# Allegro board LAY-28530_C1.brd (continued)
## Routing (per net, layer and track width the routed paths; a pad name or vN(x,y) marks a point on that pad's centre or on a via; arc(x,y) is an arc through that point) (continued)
N24275210: length 20.7
  TOP w0.127: U21.Y16 134.6,60.81 v2(134.2,60.41)
  BOTTOM w0.305: C464.1 125.66,55.04 131.03,60.41 v2(134.2,60.41)
  BOTTOM w0.381: R330.1 117.02,55.17 117.4,55.55 C467.1 121.47,55.55 121.98,55.04 C465.1 C464.1
N24275332: length 8.1
  BOTTOM w0.381: C328.2 C329.2 120.2,72.06 C330.2 R305.1
N24275468: length 8.1
  BOTTOM w0.381: C464.2 C465.2 122.23,53.52 121.47,52.75 C467.2 R336.1
N24288324: length 28.3
  TOP w0.203: U5.12 v1(101.24,137.59) ; U5.1 v1(105.63,137.59)
  L4_INT2 w0.508: v1(101.24,137.59) 102,136.83 104.87,136.83 v1(105.63,137.59)
  BOTTOM w0.508: C203.2 105.34,137.29 v1(105.63,137.59) 106.99,137.59 108.26,136.32 108.26,134.29 106.61,132.64 106.61,125.02 105.85,124.25 R225.1 R226.2 ; v1(101.24,137.59) 101.28,137.55 C206.2
N24289313: length 9.4
  TOP w0.508: R66.1 R74.1 C48.1 C51.2 105.34,122.35 104.58,123.11 L14.2
N24289334: length 4
  TOP w0.203: 104.2,129.72 104.03,129.88 U5.32
  TOP w0.508: L14.1 104.58,129.33 104.2,129.72
N24291582: length 12.2
  TOP w0.203: U5.45 107.13,134.78 107.75,134.16 R40.1 108.39,133.53 108.77,133.14 v1(109.02,133.14) 109.53,133.14 110.67,132 110.67,131.62 111.05,131.24 C36.1 115.25,131.24 115.54,131.53 Y2.1
N24291591: length 8.4
  TOP w0.203: Y2.3 113.13,134.63 112.83,134.92 v1(112.83,135.3) 112.45,135.68 C26.1 R40.2 108.13,135.68 107.63,135.18 U5.46
N24291955: length 5.8
  TOP w0.152: R59.1 98.74,129.21 v1(99.62,129.21) 100.51,129.21 101.63,130.33 U5.26
  BOTTOM w0.152: R217.1 98.74,128.45 99.5,129.21 v1(99.62,129.21)
N24292790: length 3.2
  TOP w0.203: U5.48 106.9,135.98 108.26,137.34 109.02,137.34
N24294529: length 3.4
  BOTTOM w0.254: D12.2 115.08,5.38 R401.2
N24294558: length 5.2
  BOTTOM w0.203: R396.2 C607.1
  BOTTOM w0.254: C607.1 114.1,7.29 114.39,7 D12.1
N24301989: length 27.2
  TOP w0.203: v1(122.23,137.72) 122.24,137.72 122.44,137.51 U6.12 ; v1(126.84,137.68) U6.1
  L3_INT1 w0.508: v1(122.23,137.72) 122.23,137.34 122.61,136.95 126.04,136.95 126.76,137.68 v1(126.84,137.68) 127.31,137.21 127.31,127.05 v1(124.39,124.13)
  BOTTOM w0.508: C201.2 122.48,137.46 v1(122.23,137.72) ; v1(124.39,124.13) R223.1 R224.2 ; C202.2 126.68,137.51 v1(126.84,137.68)
N24302177: length 11.2
  TOP w0.381: L15.2 127.95,124.89 ; L15.2 130.11,124.03 ; L15.2 125.79,124.03
  TOP w0.508: 130.61,124.38 C46.1 R71.1 130.61,126.16 ; 128.2,122.98 127.95,123.24 L15.2 ; R64.1 130.61,127.81 ; C50.2 130.61,122.98
N24302183: length 5.2
  TOP w0.203: 125.37,129.88 125.24,130 U6.32
  TOP w0.508: L15.1 127.95,127.68 127.31,128.32 126.93,128.32 125.37,129.88
N24302493: length 10.2
  TOP w0.203: Y1.1 135.1,133.06 C33.1 v1(133.91,133.02) 133.41,133.53 130.87,133.53 130.1,134.29 R39.1 129.22,134.29 128.72,134.78 U6.45
N24302533: length 7
  TOP w0.203: Y1.3 132.47,137.17 v1(132.14,136.83) 131.5,136.19 C25.1 R39.2 129.47,135.81 128.84,135.18 U6.46
N24302727: length 2.9
  TOP w0.203: R28.2 129.09,137.46 128.58,136.95 128.58,136.45 128.11,135.98 U6.48
N24303060: length 6.8
  BOTTOM w0.254: D13.2 121.47,6.99 R395.2
N24303062: length 5.1
  BOTTOM w0.203: C604.1 R394.2
  BOTTOM w0.254: R394.2 124.01,7.01 D13.1
N24307470: length 3.8
  TOP w0.104: U6.40 128.26,132.78 128.3,132.83 128.49,132.83 v1(128.95,132.37) 129.08,132.37 129.38,132.68 129.51,132.68 129.96,132.23 130.38,132.23 C37.2
N24307585: length 3.9
  TOP w0.104: U6.41 128.26,133.18 128.3,133.13 128.89,133.13 129.04,133.28 v1(129.04,133.41) 129.11,133.35 129.27,133.35 130.08,132.53 130.38,132.53 C30.2
N24320723: length 7.4
  TOP w0.127: U21.W3 v2(135,71.61)
  BOTTOM w0.127: v2(135,71.61) 134.6,72.01 134.6,72.58 134.6,73.5
  BOTTOM w0.152: R278.2 133.91,77.52 133.91,75.87 134.3,75.49 R288.2 134.55,75.07 134.6,75.03 134.6,73.5
N24320726: length 5.8
  TOP w0.127: U21.T4 v2(137.4,70.81)
  BOTTOM w0.104: 138.74,73.58 138.74,73.45
  BOTTOM w0.127: v2(137.4,70.81) 137.4,70.84 138.11,71.55 C331.1 138.11,72.82
  BOTTOM w0.152: 138.74,73.45 138.11,72.82 ; R285.2 138.74,73.58
N24320797: length 8.4
  TOP w0.127: U21.V5 v2(135.8,70.01)
  BOTTOM w0.122: 131.37,72.06 131.63,71.8 132.39,71.8 133,71.19 133,70.56 133.15,70.41
  BOTTOM w0.127: v2(135.8,70.01) 135.4,70.41 133.15,70.41
  BOTTOM w0.152: R296.2 130.74,72.69 131.37,72.06
N24320800: length 5
  TOP w0.127: U21.V3 v2(135.8,71.61)
  BOTTOM w0.127: v2(135.8,71.61) 135.4,72.01 135.4,73.54
  BOTTOM w0.152: 135.4,73.54 135.4,74.55 R287.2
N24320803: length 7.4
  TOP w0.152: U21.U4 v2(136.6,70.81)
  BOTTOM w0.122: 133.41,72.18 132.77,72.18 131.96,73 131.96,73.58
  BOTTOM w0.127: v2(136.6,70.81) 136.2,71.21 134,71.21 133.8,71.41 133.8,71.79 133.41,72.18
  BOTTOM w0.152: 131.96,73.58 R295.2
N24320806: length 5.1
  TOP w0.127: U21.U3 v2(136.6,71.61)
  BOTTOM w0.127: 136.2,73.58 136.2,72.01 v2(136.6,71.61)
  BOTTOM w0.152: 136.2,73.58 136.2,73.83 137.47,75.11 R286.2
N24322101: length 3.7
  TOP w0.152: U5.44 106.9,134.38 107.37,133.91 107.37,132.26 R50.1
N24325827: length 3.3
  TOP w0.178: v1(137.09,53.01) 136.2,53.9 U21.V23
  BOTTOM w0.152: v1(137.09,53.01) R342.2
N24331550: length 1.7
  TOP w0.127: U37.B9 v2(164.66,26.5)
  BOTTOM w0.127: 165.16,26.85 165.01,26.85 v2(164.66,26.5)
  BOTTOM w0.152: R371.2 165.16,26.85
N24334551: length 3.4
  TOP w0.152: v1(140.14,53.13) 141,53.99 U21.M23
  BOTTOM w0.152: v1(140.14,53.13) 140.26,53.01 R339.2
N24334558: length 3.5
  TOP w0.152: U21.N23 140.2,53.95 v1(140.14,53.9)
  BOTTOM w0.152: R338.2 141.28,52.75 v1(140.14,53.9)
N24334565: length 4.4
  TOP w0.152: U21.R22 138.6,56.01 v2(138.19,55.61)
  BOTTOM w0.127: 139.25,54.4 139.25,54.56 v2(138.19,55.61)
  BOTTOM w0.152: R340.2 139.25,54.4
N24334572: length 3.3
  TOP w0.178: v1(137.6,53.52) 137.6,53.64 137.8,53.84 U21.T23
  BOTTOM w0.152: R341.2 138.11,53 v1(137.6,53.52)
N24340384: length 1.5
  TOP w0.127: U36.B9 v2(150.69,26.5)
  BOTTOM w0.305: 151.57,26.72 150.91,26.72 v2(150.69,26.5)
N24342556: length 1.6
  TOP w0.127: U35.B9 v2(136.72,26.5)
  BOTTOM w0.129: R374.2 136.81,26.59 v2(136.72,26.5)
N24344964: length 1.7
  TOP w0.127: U34.B9 v2(122.75,26.5)
  BOTTOM w0.127: 123.75,26.72 122.97,26.72 v2(122.75,26.5)
N24364084: length 2.4
  TOP w0.152: U20.16 v1(196.92,72.93)
  BOTTOM w0.152: R301.1 197.06,73.07 v1(196.92,72.93)
N24368311: length 1.4
  TOP w0.127: U16.C3 v2(195.03,89.06)
  BOTTOM w0.127: v2(195.03,89.06) 195.26,89.29 R243.1
N24370219: length 2.4
  TOP w0.152: U14.9 v1(191.32,96.14)
  BOTTOM w0.152: R239.1 v1(191.32,96.14)
N24370226: length 2.4
  TOP w0.152: U14.1 v1(200.21,102.61)
  BOTTOM w0.152: 200.21,101.65 v1(200.21,102.61)
N24371075: length 13.5
  TOP w0.127: U21.H1 144.97,73.58
  TOP w0.152: 144.97,73.58 145.22,73.84 149.03,73.84 v2(150.3,75.11)
  BOTTOM w0.152: v2(150.3,75.11) 151.19,75.11 153.35,77.26 R282.2
N24377296: length 6.7
  TOP w0.081: 189.76,14.53 189.76,13.46 U39.C2
  TOP w0.152: 189.76,14.53 189.76,15.25 190.18,15.67 C140.1 C141.1
N24378188: length 103.6
  TOP w0.109: L4.4 196.64,152.34 196.92,152.05 196.92,151.13 196.46,150.67 196.27,150.67 196.02,150.92 v1(196.02,151.05)
  TOP w0.127: U21.D1 v2(147.8,72.41)
  L3_INT1 w0.109: v2(147.8,72.41) 147.52,72.68 147.52,73.47 153.86,79.81 153.86,82.47 185.86,114.48 185.86,123.37 196.91,134.41 196.91,148.64 196.91,148.64 196.91,150.41 196.59,150.74 196.33,150.74 v1(196.02,151.05)
N24378195: length 103.5
  TOP w0.109: v1(196.02,150.16) 196.02,150.29 196.18,150.45 196.56,150.45 197.15,151.04 197.15,152.05 197.43,152.34 L4.1
  TOP w0.122: U21.D2 v2(147,72.41)
  L3_INT1 w0.109: v2(147,72.41) 147.27,72.68 147.27,73.58 153.6,79.91 153.6,82.58 185.6,114.58 185.6,123.47 196.65,134.52 196.65,148.69 196.65,148.69 196.65,150.31 196.48,150.48 196.34,150.48 v1(196.02,150.16)
N24378208: length 9.4
  TOP w0.109: L4.3 196.64,155.35 196.92,155.64 196.92,158.05 196,158.97 J2.A3
  BOTTOM w0.109: J2.A3 196,158.97 196.89,158.08 196.89,157 196.09,156.21 U40.1
N24378216: length 9.4
  TOP w0.109: J2.A2 197.15,158.12 197.15,155.64 197.43,155.35 L4.2
  BOTTOM w0.109: J2.A2 197.11,158.08 197.11,156.94 197.97,156.08 U40.3
N24378377: length 12.3
  TOP w0.508: 199.73,156.03 L1.2 199.73,154.71 ; J2.A1 201.64,158.97 ; J2.A1 199.36,158.97 ; J2.A1 200.5,157.83
  BOTTOM w0.508: U40.5 197.03,151.56 197.39,151.2 198.96,151.2 199.45,151.69 199.45,153.21 v1(200.46,154.23)
N24378560: length 3.9
  TOP w0.762: J2.A4 194.24,158.23 L2.2
N24378635: length 4.8
  TOP w0.127: U21.E3 v2(147,71.61)
  BOTTOM w0.127: v2(147,71.61) 146.59,72.01 146.59,73.58
  BOTTOM w0.152: 146.59,73.58 146.23,73.94 R298.2 C323.1
N24378650: length 1.4
  BOTTOM w0.152: R284.1 C323.2
N24378685: length 7.6
  TOP w0.152: U21.C3 148.19,71.21 v2(148.6,71.61)
  BOTTOM w0.127: v2(148.6,71.61) 149,72.01 149,73.58 149,73.58
  BOTTOM w0.152: R271.1 149.66,76.91 149,76.25 149,73.58
N24379174: length 89.9
  TOP w0.127: U21.E4 v2(147,70.81)
  L3_INT1 w0.127: v2(147,70.81) 146.6,71.21 146.6,74.07 150.17,77.65 150.17,80.06 184.97,114.86 184.97,133.02 v1(190.94,138.99)
  BOTTOM w0.152: R199.1 190.18,139.75 v1(190.94,138.99)
N24379185: length 95.9
  TOP w0.127: U21.F4 v2(146.2,70.81)
  TOP w0.152: v1(189.79,138.99) 190.3,139.49 R25.1 189.79,140.26 188.4,141.65 188.4,145.34 188.64,145.58 U4.2
  L3_INT1 w0.127: v1(189.79,138.99) 184.59,133.78 184.59,114.98 149.79,80.19 149.79,77.77 145.8,73.78 145.8,71.21 v2(146.2,70.81)
N24379468: length 17.5
  TOP w0.254: 193.36,146.1 193.35,146.08 U4.10 192.42,146.82 192.46,146.86
  TOP w0.508: 202.88,148.52 R11.1 ; R11.1 203.63,149.4 ; R11.1 202.88,150.28 ; 199.61,146.13 C14.1 ; C14.1 200.72,144.07 ; C14.1 201.82,146.13 ; 201.92,154.66 L1.1 ; L1.1 202.72,155.37 ; L1.1 201.92,156.08 ; 195.12,146.1 C12.1 194.24,146.85 ; 202.92,151.41 D5.C ; D5.C 203.69,152.32 ; D5.C 202.92,153.24 ; 195.27,146.23 C11.1 ; C11.1 196.14,146.97 ; C11.1 197.02,146.23
N24379558: length 103.1
  TOP w0.305: R10.1 199.57,148.38 v1(199.19,148) ; R10.1 R11.2 ; R10.1 199.53,149.45 D5.A ; v2(149.4,72.41) 149,72.01 U21.B2
  L3_INT1 w0.305: v2(149.4,72.41) 149.4,72.43 154.62,77.65 154.62,80.82 160.33,86.54 160.33,87.93 187,114.6 187,123.11 198.56,134.67 198.56,147.37 v1(199.19,148)
N24379631: length 4.8
  TOP w0.254: R22.2 193.99,143.05 193.22,143.81 193.22,145.34 192.98,145.58 U4.9
N24380059: length 5.2
  TOP w0.152: U4.3 188.91,145.08 188.78,144.96 188.78,142.16 189.03,141.91 R19.1
N24380394: length 8.1
  BOTTOM w0.254: R199.2 R198.1 v1(192.79,142.92)
  BOTTOM w0.381: v1(192.79,142.92) 193.48,142.24 Q16.3 195.31,142.24 195.56,141.99 196.6,141.99 197.03,142.42 C193.2
N24389900: length 8.6
  TOP w0.127: v2(150.2,70.01) 149.8,69.61 U21.A5
  BOTTOM w0.127: 150.55,70.79 150.2,70.43 v2(150.2,70.01)
  BOTTOM w0.152: 150.55,70.79 151.06,71.3 151.06,71.68 153.85,74.47 R297.1
N24390647: length 16
  TOP w0.127: U21.F9 v2(146.2,66.81)
  BOTTOM w0.127: v2(146.2,66.81) 146.6,66.41 147.16,66.41 147.39,66.17 147.39,66.07 147.4,66.07 147.4,65.81 147.6,65.61 149.12,65.61
  BOTTOM w0.152: 149.12,65.61 149.41,65.33 R323.2
N24391453: length 13.2
  TOP w0.127: v2(146.2,58.01) 145.8,58.41 U21.F19
  BOTTOM w0.127: 154.62,57.83 154.39,57.61 146.59,57.61 146.2,58 v2(146.2,58.01)
  BOTTOM w0.152: 154.62,57.83 154.74,57.96 158.55,57.96
N24392141: length 83.9
  TOP w0.127: U21.F18 145.8,59.21 v2(146.2,58.81)
  TOP w0.152: R163.2 R164.2 206.69,29.77 205.62,30.83 Q10.3 v1(202.49,30.83)
  BOTTOM w0.127: 154.68,58.6 154.5,58.41 146.6,58.41 v2(146.2,58.81)
  BOTTOM w0.152: v1(202.49,30.83) 202.49,31.42 200.46,33.45 184.33,33.45 182.68,35.1 174.94,35.1 172.14,37.89 172.14,44.63 168.33,48.44 168.33,55.42 165.16,58.6 154.68,58.6
N24402189: length 47.1
  TOP w0.127: U21.E8 v2(147,67.61)
  TOP w0.152: v1(167.95,45.64) 171.33,42.26 Q8.3 R150.2
  L4_INT2 w0.127: v2(147,67.61) 147,67.61 147.4,67.21 151.33,67.21 155.63,62.91 155.63,61.64 158.81,58.47 158.81,56.44 161.85,53.39 166.05,53.39 167.95,51.48 v1(167.95,45.64)
N24414694: length 2.4
  TOP w0.203: TP2.1 90.1,149.4 89,150.5 U1.30
N24414710: length 1.4
  TOP w0.203: U1.2 89.4,156.07 TP1.1
N24418365: length 2.3
  BOTTOM w0.152: R367.2 v1(180.02,41.04) Q24.1
N24421074: length 2.2
  TOP w0.152: v1(209.36,87.43) SW1.16
  BOTTOM w0.152: R244.2 209.36,87.42 v1(209.36,87.43)
N24421076: length 2.2
  TOP w0.152: v1(209.36,86.16) SW1.15
  BOTTOM w0.152: R250.2 209.36,86.15 v1(209.36,86.16)
N24421078: length 2.2
  TOP w0.152: v1(209.36,84.89) SW1.14
  BOTTOM w0.152: R252.2 209.36,84.88 v1(209.36,84.89)
N24421080: length 2.2
  TOP w0.152: v1(209.36,83.62) SW1.13
  BOTTOM w0.152: R254.2 209.36,83.61 v1(209.36,83.62)
N24421082: length 2.2
  TOP w0.152: v1(209.36,82.34) SW1.12
  BOTTOM w0.152: R256.2 209.36,82.34 v1(209.36,82.34)
N24421084: length 2.2
  TOP w0.152: v1(209.36,81.07) SW1.11
  BOTTOM w0.152: R261.2 209.36,81.07 v1(209.36,81.07)
N24421086: length 2.2
  TOP w0.152: v1(209.36,79.8) SW1.10
  BOTTOM w0.152: R267.2 209.36,79.8 v1(209.36,79.8)
N24421088: length 2.2
  TOP w0.152: v1(209.36,78.53) SW1.9
  BOTTOM w0.152: v1(209.36,78.53) 209.36,78.53 R275.2
N24421090: length 2.4
  TOP w0.152: SW2.16 v1(209.23,74.86)
  BOTTOM w0.152: R293.2 209.24,74.85 v1(209.23,74.86)
N24421092: length 2.4
  TOP w0.152: SW2.15 v1(209.23,73.59)
  BOTTOM w0.152: v1(209.23,73.59) 209.24,73.58 R300.2
N24421094: length 2.4
  TOP w0.152: SW2.14 v1(209.23,72.32)
  BOTTOM w0.152: v1(209.23,72.32) 209.24,72.31 R303.2
N24421096: length 2.4
  TOP w0.152: SW2.13 v1(209.23,71.05)
  BOTTOM w0.152: v1(209.23,71.05) 209.24,71.04 R307.2
N24421098: length 2.4
  TOP w0.152: SW2.11 v1(209.23,68.5)
  BOTTOM w0.152: R313.2 209.24,68.5 v1(209.23,68.5)
N24421100: length 2.4
  TOP w0.152: SW2.12 v1(209.23,69.77)
  BOTTOM w0.152: v1(209.23,69.77) 209.24,69.77 R311.2
N24421104: length 2.4
  TOP w0.152: SW2.9 v1(209.23,65.96)
  BOTTOM w0.152: v1(209.23,65.96) 209.24,65.96 R318.2
N24422044: length 23.5
  TOP w0.122: U21.E7 146.6,68.01 v2(147,68.41)
  L4_INT2 w0.127: v1(161.73,55.04) 161.09,55.67 160.71,55.67 159.19,57.2 159.19,58.6 156.01,61.77 156.01,63.04 151.04,68.01 147.4,68.01 v2(147,68.41)
  BOTTOM w0.152: TP41.1 v1(161.73,55.04)
N24422127: length 18.2
  TOP w0.127: U21.H19 144.2,58.41 v2(144.6,58.01)
  L4_INT2 w0.127: v2(144.6,58.01) 144.99,57.61 144.99,55.26 145.6,54.66 155.5,54.66 v1(157.66,52.5)
  BOTTOM w0.152: 158.55,52.5 v1(157.66,52.5)
N24422137: length 21.9
  TOP w0.305: v2(143.8,58.81) 143.4,59.21 U21.J18
  L4_INT2 w0.127: v1(157.79,50.21) 157.79,50.85 154.74,53.9 144.71,53.9 143.39,55.21 143.39,58.41 v2(143.8,58.81)
  BOTTOM w0.152: 158.55,50.21 v1(157.79,50.21)
N24426897: length 11.6
  TOP w0.127: v2(147.8,62.01) 148.19,62.41 U21.C14
  BOTTOM w0.127: v2(147.8,62.01) 148.2,62.41 150.3,62.41
  BOTTOM w0.152: R325.1 154.49,61.9 153.98,62.41 150.3,62.41
N24433996: length 2.9
  TOP w0.152: SW3.16 210.62,62.06 v1(210.62,62.05) 210.97,62.41 R130.2
N24433998: length 3
  TOP w0.152: SW3.15 210.62,60.79 v1(210.62,60.78) 211.1,61.26 R131.2
N24434000: length 2.4
  TOP w0.152: R132.1 210.85,59.74 v1(210.62,59.51) 210.62,59.52 SW3.14
N24434027: length 2.4
  TOP w0.152: SW3.13 210.65,58.25 v1(210.65,58.24) 210.81,58.09 R133.1
N24434063: length 2.5
  TOP w0.152: SW3.12 210.62,56.97 v1(210.62,56.96) 211.15,56.44 R136.1
N24434090: length 2.7
  TOP w0.152: SW3.11 210.48,55.7 v1(210.62,55.55) 211.38,54.79 R139.1
N24434117: length 2.9
  TOP w0.152: SW3.10 210.62,54.43 v1(210.62,54.42) 210.62,54.28 R141.1
N24442993: length 13.8
  TOP w0.127: U21.W7 v2(135,68.41)
  BOTTOM w0.127: v2(135,68.41) 134.6,68.01 131.99,68.01 131.76,68.25 131.37,68.25
  BOTTOM w0.152: R309.1 124.14,69.9 129.47,69.9 131.12,68.25 131.37,68.25
N24443017: length 22
  TOP w0.127: U21.V15 136.2,61.61 v2(135.8,61.21)
  L4_INT2 w0.127: v2(135.8,61.21) 135.4,60.81 132.32,60.81 127.95,56.44 v1(117.4,56.44)
  BOTTOM w0.152: v1(117.4,56.44) R329.1
N24480234: length 2.6
  TOP w0.254: U7.6 193.92,135.05 193.86,135.11 R38.1 R33.1
N24480259: length 28.6
  TOP w0.254: U7.4 194.85,133.5 v1(195,133.65) ; v1(190.18,131.37) 189.67,131.87 189.67,132.51 190.2,133.05 U7.10
  TOP w0.381: R54.2 v1(197.8,130.99) ; R45.2 197.67,133.4 v1(197.92,133.14)
  TOP w0.508: R33.2 C19.2 v1(191.7,138.48)
  BOTTOM w0.508: v1(190.18,131.37) 192.97,131.37 193.99,130.35 197.16,130.35 v1(197.8,130.99) 197.92,131.11 v1(197.92,133.14) 197.41,133.65 v1(195,133.65) 191.7,136.95 v1(191.7,138.48)
N24480273: length 1.4
  BOTTOM w0.254: C217.1 190.3,134.29 189.86,134.73 v1(189.86,135.11)
N24480332: length 3.4
  TOP w0.254: R60.2 C41.1 194.11,131.43 193.92,131.62 U7.1
N24480366: length 5.1
  TOP w0.254: U7.5 194.41,133.95 195,134.54 v1(195,135.3) 195,135.81 195.26,136.07 R36.2 R29.2
N24480391: length 2.8
  TOP w0.254: U7.9 189.89,133.5 v1(189.54,133.14)
  BOTTOM w0.254: C217.2 189.67,133.27 v1(189.54,133.14)
N24480399: length 3.3
  TOP w0.254: U7.3 195.54,133.05 R45.1 R44.2
N24480593: length 4.9
  TOP w0.254: C43.2 R54.1 R48.2 194.75,132.26 194.41,132.6 U7.2
N24480595: length 1.1
  TOP w0.203: R48.1 C32.2
N24506779: length 3.4
  TOP w0.305: v1(90.35,47.55) 90.6,47.31 U28.21
  BOTTOM w0.305: C478.1 90.48,47.42 v1(90.35,47.55)
N24506783: length 1
  BOTTOM w0.508: C474.2 v1(89.46,48.94)
N24506809: length 2.2
  TOP w0.254: U28.20 91.49,47.81 v1(91.37,47.93)
  BOTTOM w0.254: v1(91.37,47.93) 91.5,48.05 C474.1
N24506829: length 5
  TOP w0.254: R148.1 90.73,44.5 92.04,45.8 U28.24
  TOP w0.381: R148.1 R149.2 C106.2
N24506871: length 2.1
  TOP w0.254: U28.3 96.18,46.8 96.35,46.63 v1(96.45,46.63)
  BOTTOM w0.254: R359.1 v1(96.45,46.63)
N24506911: length 4
  TOP w0.254: U28.4 97.96,47.31 R145.1
  TOP w0.305: R147.2 R145.1
N24506929: length 4.2
  TOP w0.254: C105.1 97.47,43.74 96.96,44.24 96.96,45.13 95.79,46.3 U28.2
N24509763: length 4.2
  TOP w0.254: v1(105.47,38.91) 106.09,39.53 U29.21
  BOTTOM w0.254: C480.1 106.1,39.55 v1(105.47,38.91)
N24509767: length 2
  BOTTOM w0.508: v1(104.96,37.51) 104.2,38.28 C481.2
N24509789: length 2.4
  TOP w0.254: v1(105.47,40.05) 105.59,40.18 U29.20
  BOTTOM w0.508: v1(105.47,40.05) 105.34,40.18 C481.1
N24509805: length 4.5
  TOP w0.254: C109.2 R152.2 R151.1 108.01,40.05 107.59,40.47 U29.24
N24509853: length 2
  TOP w0.254: v1(106.74,45.01) 106.59,44.86 U29.3
  BOTTOM w0.254: R361.1 v1(106.74,45.01)
N24509885: length 2.2
  TOP w0.254: U29.4 106.09,45.25 106.48,45.64 R146.2
N24509913: length 2.5
  TOP w0.254: C103.1 108.13,45.51 107.09,44.47 U29.2
N24514524: length 6.3
  TOP w0.254: U22.23 91.22,65.55 91.75,66.09 92.26,66.09 92.77,65.58 TP12.1
N24515056: length 12.3
  TOP w0.508: R145.2 v1(99.5,48.56)
  BOTTOM w0.508: J18.2 93.91,40.82 97.72,44.63 97.72,46.78 v1(99.5,48.56)
N24544266: length 2.3
  TOP w0.152: TP50.1 87.47,22.11 U38.3
N24551325: length 10.1
  TOP w0.152: SW4.1 212.73,157.61 210.37,155.24 J6.1 R9.1
N24551347: length 9.7
  TOP w0.152: 213.16,149.53 R9.2 Q1.3 210.88,147.57 210.32,148.13 208.59,148.13 208.03,147.57 U3.3 207.64,149.21 R8.2
N24582130: length 8.4
  TOP w0.104: U21.AC9 132.01,66.6 131.63,66.6 131.55,66.52 130.64,66.52 130.36,66.8 126.97,66.8 126.29,66.13 125.76,66.13 125.66,66.02 125.66,65.78 v1(125.74,65.71)
  BOTTOM w0.104: C377.1 v1(125.74,65.71)
N24582194: length 3.9
  TOP w0.127: U21.AB11 v2(132.6,65.21)
  BOTTOM w0.104: C366.1 130.1,66.22 130.21,66.11 130.77,66.11 130.87,66.01 131.27,66.01 131.31,65.98 132.07,65.98 132.31,65.74 132.31,65.49 v2(132.6,65.21)
N24582197: length 3.5
  TOP w0.127: U21.AC11 v2(131.8,65.21)
  BOTTOM w0.104: v2(131.8,65.21) 132.08,65.49 132.08,65.64 131.98,65.75 131.31,65.75 131.27,65.71 130.74,65.71 130.64,65.81 130.21,65.81 130.1,65.7 C381.1
N24582200: length 9.2
  TOP w0.104: U21.AB9 132.58,66.82 130.77,66.82 130.49,67.1 126.84,67.1 126.17,66.43 125.76,66.43 125.66,66.54 125.66,66.75 v1(125.71,66.8)
  BOTTOM w0.104: C365.1 125.53,66.72 125.61,66.8 v1(125.71,66.8)
N24582275: length 12.4
  TOP w0.127: U21.W9 v2(135,66.81)
  BOTTOM w0.104: v2(135,66.81) 134.71,66.53 134.71,66.28 134.47,66.04 134.01,66.04 133.56,66.49 131.4,66.49 131.37,66.46 131.22,66.46 129.57,68.1 124.88,68.1 124.77,67.99 C355.2
N24582286: length 12
  TOP w0.127: U21.Y9 v2(134.2,66.81)
  BOTTOM w0.104: C344.2 124.77,68.5 124.88,68.4 129.7,68.4 131.34,66.76 131.5,66.76 131.53,66.72 133.66,66.72 134.11,66.27 134.38,66.27 134.48,66.38 134.48,66.53 v2(134.2,66.81)
N24582369: length 6
  TOP w0.127: v2(134.2,62.81) 134.6,63.21 U21.Y13
  BOTTOM w0.104: C403.2 130.1,63.67 130.21,63.78 131.02,63.78 131.25,63.55 133.35,63.55 133.38,63.59 134.13,63.59 134.48,63.23 134.48,63.1 v2(134.2,62.81)
N24582387: length 6.4
  TOP w0.127: U21.W13 135.4,63.21 v2(135,62.81)
  BOTTOM w0.104: C391.2 130.1,64.19 130.21,64.08 131.14,64.08 131.37,63.85 133.35,63.85 133.38,63.81 134.22,63.81 134.71,63.34 134.71,63.1 v2(135,62.81)
N24582412: length 8.6
  TOP w0.127: U21.V8 v2(135.8,67.61)
  BOTTOM w0.127: 131.37,67.87 131.63,67.87 132.28,67.21 135.4,67.21 v2(135.8,67.61)
  BOTTOM w0.152: TP30.1 129.72,69.14 130.99,67.87 131.37,67.87
N24582419: length 13.5
  TOP w0.127: U21.U10 v2(136.6,66.01)
  BOTTOM w0.127: 131.25,69.77 132.67,69.77 133.06,69.38 133.93,69.38 134.5,68.81 135.96,68.81 136.2,68.58 136.2,66.64 136.2,66.64 136.2,66.34 136.53,66.01 v2(136.6,66.01)
  BOTTOM w0.152: TP28.1 129.72,71.3 131.25,69.77
N24582434: length 5.8
  TOP w0.127: v2(135,60.41) 135.4,60.81 U21.W16
  BOTTOM w0.127: 133.77,60.01 134.6,60.01 v2(135,60.41)
  BOTTOM w0.152: TP37.1 130.74,59.36 131.4,60.02 133.76,60.02 133.77,60.01
N24582441: length 15.6
  TOP w0.127: v2(136.6,62.01) 137,62.41 U21.U14
  BOTTOM w0.127: 131.43,60.81 135.18,60.81 135.4,61.02 135.4,62.24 135.57,62.41 136.2,62.41 v2(136.6,62.01)
  BOTTOM w0.152: 131.43,60.81 130.54,60.81 126.29,56.56 TP42.1
N24584329: length 2.6
  TOP w0.129: TP18.1 99.04,23.17
  TOP w0.152: U38.41 98.48,22.61 99.04,23.17
N24605281: length 2.6
  TOP w0.152: TP57.1 88.25,23.11 U38.1
N24616249: length 7.7
  TOP w0.254: R52.1 C44.1 174.55,129.33 v1(176.08,130.86) 176.12,130.9 Y3.3
N24647838: length 2.3
  BOTTOM w0.152: Q25.1 v1(176.21,40.99) R368.2
N24648256: length 2.2
  TOP w0.152: R153.2 v1(204.78,34.08) Q10.1
N24648262: length 2.2
  TOP w0.152: R154.2 v1(208.72,34.08) Q11.1
N24652945: length 43.8
  TOP w0.508: Q4.1 v1(101.15,111.17) ; Q20.3 71.61,110.28 v1(73.34,110.28) R236.1 ; v1(101.15,103.55) Q5.1
  BOTTOM w0.508: v1(73.34,110.28) 74.22,111.17 v1(101.15,111.17) v1(101.15,103.55)
N24653996: length 5.2
  TOP w0.508: Q19.4 R230.1 R231.2
N24654004: length 21.2
  TOP w0.508: v1(81.46,97.97) R97.1 Q6.1 ; Q19.6 70.67,104.19 v1(71.3,103.55) 71.94,104.19 Q19.5
  BOTTOM w0.508: v1(71.3,103.55) 75.88,103.55 v1(81.46,97.97)
N24658856: length 5.1
  TOP w0.178: U21.Y23 134.6,54.07 133.79,53.26 v1(133.66,53.26)
  BOTTOM w0.152: v1(133.66,53.26) 134.93,53.26 R343.2
N24665133: length 11.4
  BOTTOM w0.508: 175.82,103.17 175.82,101.16 ; 175.82,101.16 174.55,101.16 ; 175.82,101.16 176.74,101.16 177.09,101.52 177.09,103.17 ; 174.55,103.17 174.55,101.16 ; 174.55,101.16 173.64,101.16 173.28,101.52 173.28,103.17
N24674533: length 21.9
  TOP w0.508: Q7.4 173.67,89.5 174.17,88.99 v1(176.21,88.99) Q7.2
  BOTTOM w0.508: Q22.8 177.48,89.33 177.14,88.99 v1(176.21,88.99) ; v1(176.21,88.99) Q22.7 C288.2 R241.2 ; v1(176.21,88.99) 175.02,87.81 174.43,87.81 173.67,87.04 Q22.4
N24674544: length 18.9
  BOTTOM w0.508: Q22.5 173.67,89.08 173.79,88.95 174.68,88.95 174.94,89.2 Q22.6 C289.2 R242.2 172.4,92.76 172.01,93.14 172.01,95.04 172.9,95.93 ; Q21.2 175.82,96.31 175.44,95.93 172.9,95.93 ; Q21.4 173.28,96.31 172.9,95.93
N24675233: length 6.6
  BOTTOM w0.152: Q22.2 176.21,83.11 174.68,81.58 R258.2 R266.2
N24678302: length 4.5
  TOP w0.508: Q23.1 76.26,52.31 R248.2 R247.2
N24861043: length 1.8
  TOP w0.152: R16.2 Q1.1
N24873583: length 1.7
  TOP w0.152: Q13.1 R179.1
N24876902: length 1.7
  BOTTOM w0.152: Q14.1 R194.1
N24877168: length 2.4
  BOTTOM w0.152: R193.2 206.18,149.27 205.67,148.77 Q15.1
N24891529: length 18.5
  TOP w0.127: U21.A3 149.8,71.21 v2(150.2,71.61)
  BOTTOM w0.127: 150.55,73.45 149.8,72.7 149.8,72.01 v2(150.2,71.61)
  BOTTOM w0.152: 150.55,73.45 153.35,76.25 159.31,76.25 162.87,79.8 R269.2
N24891545: length 24
  TOP w0.305: v2(143,59.61) 143.4,60.01 U21.J17
  L4_INT2 w0.127: v1(157.03,50.09) 157.03,50.72 154.23,53.52 144.33,53.52 142.59,55.25 142.59,59.21 v2(143,59.61)
  BOTTOM w0.152: v1(157.03,50.09) 158.04,49.07 158.55,49.07
N24892246: length 2.5
  TOP w0.152: Q8.1 v1(176.21,45.77) R142.2
N24892373: length 5
  TOP w0.152: R165.2 202.49,21 198.94,21 198.56,20.62 Q12.1
N24932777: length 24.6
  TOP w0.508: T2.1 v1(76.84,139.06)
  L4_INT2 w0.508: v1(76.84,139.06) 76.84,152.4 v1(78.42,153.97)
  BOTTOM w0.508: R1.2 v1(78.42,153.97) ; v1(76.84,139.06) 76,139.91 D24.1
N24935123: length 3.2
  BOTTOM w0.508: D24.3 75.04,146.48 R187.1
N24935830: length 1.8
  BOTTOM w0.508: 83.04,144.75 C186.2 82.29,143.69
  vias: v1(81.08,144.32) v1(81.59,144.96) v1(81.59,143.56)
N24935853: length 3.8
  BOTTOM w0.508: 85.72,143.69 C186.1 84.97,142.62 ; 85.83,141.27 R195.2 85.02,142.47
N24936812: length 4.7
  TOP w0.508: Q2.4 89.46,144.83 89.82,145.19 89.82,146.63 89.08,147.37 R14.2
N24970769: length 3.6
  TOP w0.305: R83.1 R88.1 142.44,111.92 U12.7
N24994453: length 3.2
  TOP w0.254: U11.9 135.34,104.85 R96.2 R95.1
N25019525: length 2.2
  BOTTOM w0.127: R379.1 R381.2 C535.2
N25029315: length 1.5
  BOTTOM w0.508: R186.2 C177.1
N25032157: length 94.7
  L4_INT2 w0.203: v1(161.85,9.19) 161.85,8.56 165.79,4.62 172.27,4.62 176.08,8.43 176.08,30.4 168.71,37.77 168.71,51.36 157.54,62.53 157.54,67.61 156.77,68.37 156.77,69.14 v1(157.28,69.64)
  BOTTOM w0.152: v1(157.28,69.64) 157.66,70.03 157.66,74.22 R297.2
  BOTTOM w0.254: v1(161.85,9.19) Q28.1
N25032334: length 2.5
  TOP w0.152: Q9.1 v1(180.02,45.77) R144.1
N25072149: length 3.6
  TOP w0.254: R118.2 93.78,77.65 95.07,78.94 U19.6
N25115909: length 7.1
  TOP w0.104: v1(127.11,62.48) 127.06,62.43 127.06,62.22 127.16,62.11 127.91,62.11 129.01,63.22 131.43,63.22 131.63,63.01 132,63.01 132.2,63.21 U21.AC13
  BOTTOM w0.104: v1(127.11,62.48) 127.06,62.53 C409.1
N25115912: length 8
  TOP w0.104: U21.AB13 132.99,63.21 132.57,62.78 131.31,62.78 131.18,62.91 129.13,62.91 128.03,61.81 127.16,61.81 127.06,61.7 127.06,61.44 v1(127.11,61.39)
  BOTTOM w0.104: C427.1 126.93,61.52 127.06,61.39 v1(127.11,61.39)
N25116015: length 6.6
  TOP w0.127: U21.W14 135.4,62.41 v2(135,62.01)
  BOTTOM w0.104: v2(135,62.01) 134.71,61.72 134.71,61.48 134.4,61.17 134.06,61.17 133.44,61.8 131.53,61.8 131.49,61.76 130.99,61.76 130.92,61.68 130.21,61.68 130.1,61.58 C429.2
N25116018: length 6.2
  TOP w0.127: U21.Y14 134.6,62.41 v2(134.2,62.01)
  BOTTOM w0.104: C417.2 130.1,62.09 130.21,61.98 130.79,61.98 130.87,62.06 131.37,62.06 131.41,62.02 133.53,62.02 134.16,61.4 134.31,61.4 134.48,61.57 134.48,61.72 v2(134.2,62.01)
N25118599: length 9.3
  TOP w0.508: Q20.1 68.18,108.05 R235.1 68.13,104.06 68.47,103.72 69.19,103.72 69.4,103.93 69.4,105.33
N25120670: length 5.2
  TOP w0.508: R232.1 R234.1 69.4,99.74
N25139524: length 6.3
  BOTTOM w0.254: R393.2 130.61,5.85 D14.2
N25139526: length 3.3
  BOTTOM w0.254: R392.2 132.26,9.07 132,8.8 D14.1
N25141555: length 2.5
  BOTTOM w0.254: R399.1 167.03,2.97 D15.C
N25157671: length 6.9
  TOP w0.508: J21.2 208.72,124.64 207.19,123.11 R79.2
N25157693: length 6.1
  TOP w0.305: R81.1 R82.2 C61.2 210.11,114.09 209.49,114.72 U9.4
N25157716: length 7.6
  TOP w0.305: U9.20 204.92,111.69 204.02,110.79 204.02,109.01 203.76,108.76 C75.2 203.26,108.25 203.76,107.74 D8.C
N25157741: length 8.1
  TOP w0.305: C75.1 v1(202.24,107.87)
  BOTTOM w0.305: v1(202.24,107.87) 202.24,113.84 v1(201.35,114.73)
N25157783: length 3.5
  TOP w0.305: U9.19 204.42,111.96 204.27,111.81 203.64,111.81 203.26,111.43 R91.2 C67.1
N25157815: length 4.1
  TOP w0.305: R78.1 R79.1 v1(207.19,117.9) 207.19,117.29 206.92,117.02 U9.7
N25157819: length 2.9
  TOP w0.305: U9.5 208.71,115.22 v1(209.1,115.62)
  BOTTOM w0.305: C281.1 208.59,116.13 v1(209.1,115.62)
N25157835: length 2
  TOP w0.305: U9.1 208.19,113.23 v1(208.46,112.95)
  BOTTOM w0.305: v1(208.46,112.95) 208.34,112.82 R233.2
N25157944: length 6.9
  TOP w0.305: U9.2 208.71,113.73 R89.2 R90.1 R92.2 R93.1
N25158030: length 7
  TOP w0.305: R77.1 C53.1 R80.1 209.86,118.67 208.72,117.52 208.72,116.38 208.06,115.73 U9.6
N25158044: length 1.1
  TOP w0.305: 211.38,121.08 211.38,122.22
N25168167: length 5.8
  BOTTOM w0.254: D18.C 159,4.68 157.59,6.09 Q28.3
N25168313: length 4.5
  BOTTOM w0.254: D18.A 156.46,4.94 155.63,5.76 R400.2
N25169246: length 4.5
  TOP w0.254: R22.1 R23.1 195.64,138.99 195.79,138.83 v1(195.79,138.76)
  BOTTOM w0.254: Q16.1 195.76,138.78 v1(195.79,138.76)
N25171285: length 3.9
  TOP w0.152: U5.14 99.48,135.58 98.99,136.07 98.99,137.21 98.61,137.59 R27.1
N25171337: length 2.9
  TOP w0.152: R43.1 120.07,134.67 120.98,135.58 U6.14
N25171340: length 3.4
  TOP w0.152: U6.15 121.22,135.18 R46.1
N25212963: length 3.1
  TOP w0.305: R134.1 R137.1 108.75,56.54 U26.7
N25235874: length 9.7
  TOP w0.381: C22.1 R31.2 113.72,139.11 111.01,141.82 J4.20
N25235936: length 23.9
  BOTTOM w0.635: C189.1 111.05,144.45 110.97,144.36 J4.12
  BOTTOM w1.27: J4.7 95.91,145.88 J4.1 96.93,147.97 97.82,148.87 106.38,148.87 107.07,148.17 J4.6 108.09,145.88 J4.12
N25236971: length 6.6
  TOP w0.305: J4.18 96.88,140.26 95.56,140.26 94.67,139.37 R34.2
N25238548: length 23.8
  BOTTOM w0.635: C190.1 137.56,144.36 J5.12
  BOTTOM w1.27: J5.7 120.91,145.88 J5.1 121.93,148.21 122.82,149.1 130.91,149.1 132.08,147.94 J5.6 133.09,145.88 133.09,144.36 J5.12
N25238664: length 7.7
  TOP w0.305: R35.2 119.69,136.19 120.2,136.7 120.2,138.57 J5.18
N25239505: length 8
  TOP w0.305: R32.2 C23.1 137.09,139.24 134.51,141.82 J5.20
N25263474: length 25.4
  TOP w0.127: v2(141.4,59.61) 141,60.01 U21.M17
  L4_INT2 w0.127: v1(157.92,48.44) 156.27,50.09 156.27,50.98 154.11,53.13 144.07,53.13 141.79,55.42 141.79,59.21 v2(141.4,59.61)
  BOTTOM w0.152: v1(157.92,48.44) 158.55,47.8
N25276538: length 2.7
  TOP w0.152: U5.15 99.37,135.18 98.61,135.94 R37.1
N25435604: length 38.5
  TOP w0.127: U21.L3 v2(142.2,71.61)
  TOP w0.152: R99.1 v1(163.25,96.82)
  L3_INT1 w0.127: v1(163.25,96.82) 162.49,96.82 159.06,93.39 159.06,92.38 147.76,81.07 147.76,77.77 144.33,74.34 142.68,74.34 141.79,73.45 141.79,72.02 v2(142.2,71.61)
N25440106: length 1.7
  TOP w0.152: Q11.3 R164.1
N25462949: length 5
  TOP w0.254: R120.2 94.04,75.74 96.22,77.92 U19.7
N25493237: length 3.9
  TOP w0.305: TP17.1 89.11,46.3 U28.23
N25495882: length 26.7
  TOP w0.127: U21.A17 149.8,60.01 150.55,60.01
  TOP w0.152: 150.55,60.01 151.04,60.01 156.9,54.15 164.78,54.15 167.7,51.23 TP15.1
N25614619: length 29.3
  TOP w0.127: 150.55,60.39 149.38,60.39 149,60.01 U21.B17
  TOP w0.152: 150.55,60.39 151.3,60.39 157.16,54.53 165.03,54.53 167.57,51.99 173.54,51.99 TP16.1
N25614638: length 27
  TOP w0.127: 150.55,63.63 148.62,63.63 U21.C13
  TOP w0.152: 150.55,63.63 154.28,63.63 159.06,58.85 165.79,58.85 169.6,55.04 TP13.1
N25614641: length 8.2
  TOP w0.127: U21.E13 146.6,63.21 v2(147,63.61)
  L4_INT2 w0.127: v1(152.2,60.25) 151.95,60.25 148.59,63.61 v2(147,63.61)
  BOTTOM w0.152: TP31.1 152.33,60.37 v1(152.2,60.25)
N25614652: length 9
  TOP w0.127: U21.D12 147.39,64.01 v2(147.8,64.41)
  L4_INT2 w0.127: v2(147.8,64.41) 147.8,64.4 148.27,63.93 149.79,63.93 152.84,60.88 152.84,60.32 v1(152.91,60.25)
  BOTTOM w0.152: TP32.1 153.73,60.75 153.22,60.25 v1(152.91,60.25)
N25614663: length 18.9
  TOP w0.127: U21.P17 139.4,60.01 v2(138.99,59.61)
  L3_INT1 w0.127: v1(126.04,57.45) 128.07,57.45 131.43,60.81 138.42,60.81 138.6,60.63 138.6,60.01 v2(138.99,59.61)
  BOTTOM w0.152: v1(126.04,57.45) 124.14,57.45 TP43.1
N25614680: length 18.7
  TOP w0.127: U21.F7 v2(146.2,68.41)
  L4_INT2 w0.127: v1(155,59.48) 155.12,59.61 155.12,62.02 150.74,66.41 146.83,66.41 146.6,66.64 146.6,68.01 146.2,68.41 v2(146.2,68.41)
  BOTTOM w0.152: TP35.1 157.79,59.48 v1(155,59.48)
N25614695: length 21.6
  TOP w0.127: v2(147,70.01) U21.E5
  L4_INT2 w0.127: v1(161.35,57.96) 161.35,58.21 157.16,62.41 157.16,63.42 150.97,69.61 147.39,69.61 v2(147,70.01)
  BOTTOM w0.152: TP39.1 161.47,57.83 v1(161.35,57.96)
N25614710: length 15.5
  TOP w0.127: U21.E10 v2(147,66.01)
  L4_INT2 w0.127: v1(154.11,59.48) 154.74,60.12 154.74,61.9 151.03,65.61 147.4,65.61 v2(147,66.01)
  BOTTOM w0.152: TP33.1 156.39,59.99 154.62,59.99 v1(154.11,59.48)
N25614762: length 24.2
  TOP w0.127: v2(147.8,69.21) 147.39,68.81 U21.D6
  L4_INT2 w0.127: v2(147.8,69.21) 148.19,68.81 150.75,68.81 156.39,63.17 156.39,62.02 159.57,58.85 159.57,57.45 159.95,57.07 161.73,57.07 v1(162.24,56.56)
  BOTTOM w0.152: v1(162.24,56.56) 163.51,57.83 TP40.1
N25614777: length 23.1
  TOP w0.127: U21.C6 148.19,68.81 v2(148.6,69.21)
  L4_INT2 w0.127: v1(163.12,56.18) 163.12,56.31 161.98,57.45 160.2,57.45 159.95,57.71 159.95,58.98 156.77,62.15 156.77,63.29 150.86,69.21 v2(148.6,69.21)
  BOTTOM w0.152: v1(163.12,56.18) 163.25,56.06 TP38.1
N25614880: length 12.8
  TOP w0.127: U21.M5 v2(141.4,70.01)
  BOTTOM w0.127: 140.26,73.58 140.26,72.24 140.04,72.01 139.63,72.01 139.4,71.78 139.4,69.75 139.63,69.52 140.9,69.52 141.39,70.01 v2(141.4,70.01)
  BOTTOM w0.152: 140.26,73.58 140.26,78.03 TP59.1
N25617432: length 13.4
  TOP w0.127: U21.F10 v2(146.2,66.01)
  L4_INT2 w0.127: v1(154.11,60.25) 154.11,61.9 151.19,64.81 146.75,64.81 146.6,64.96 146.6,65.6 146.2,66 v2(146.2,66.01)
  BOTTOM w0.152: TP34.1 154.62,60.75 v1(154.11,60.25)
N25617574: length 9.3
  TOP w0.127: U21.AA5 v2(133.4,70.01)
  L4_INT2 w0.127: v1(126.17,69.01) 127.17,70.01 v2(133.4,70.01)
  BOTTOM w0.152: v1(126.17,69.01) 126.29,69.14 TP24.1
N25617577: length 28.2
  TOP w0.127: U21.AA2 133.41,72.4 133.41,73.07 132.9,73.58
  TOP w0.152: 132.9,73.58 132.64,73.84 123.5,73.84 121.09,76.25 119.06,76.25 112.2,83.11 TP5.1
N25617583: length 12.9
  TOP w0.127: U21.AA4 v2(133.4,70.81)
  L4_INT2 w0.122: v2(133.4,70.81) 133.16,70.81 132.16,71.8 131.63,71.8 131.37,72.06
  L4_INT2 w0.127: v1(124.77,75.23) 125.41,74.6 128.83,74.6 131.37,72.06
  BOTTOM w0.152: R424.2 v1(124.77,75.23) R425.1
N25617586: length 12.2
  TOP w0.127: U21.Y4 v2(134.2,70.81)
  L4_INT2 w0.127: v1(126.68,75.23) 129.85,75.23 132.26,72.82 132.26,72.18 133.23,71.21 133.8,71.21 v2(134.2,70.81)
  BOTTOM w0.152: R423.2 v1(126.68,75.23) R426.1
N25617589: length 27.3
  TOP w0.127: 131.37,71.21 U21.AC3
  TOP w0.152: TP8.1 109.78,80.82 112.58,80.82 120.71,72.69 127.44,72.69 128.92,71.21 131.37,71.21
N25617590: length 25.3
  TOP w0.127: 131.37,69.61 131.63,69.61 U21.AC5
  TOP w0.152: TP11.1 113.09,78.41 119.94,71.55 122.99,71.55 124.93,69.61 131.37,69.61
N25617591: length 25.6
  TOP w0.127: U21.AC4 131.37,70.41
  TOP w0.152: TP9.1 112.71,80.06 120.45,72.31 123.75,72.31 125.66,70.41 131.37,70.41
N25617592: length 26.7
  TOP w0.127: U21.AB3 132.58,71.63 131.42,71.63 131.37,71.68
  TOP w0.152: TP7.1 112.45,81.58 120.96,73.07 127.69,73.07 129.09,71.68 131.37,71.68
N25617593: length 28
  TOP w0.127: 131.37,70.03 132.58,70.03 U21.AB5
  TOP w0.152: TP10.1 109.53,79.17 112.96,79.17 120.2,71.93 123.37,71.93 125.28,70.03 131.37,70.03
N25622344: length 4.3
  TOP w0.254: R445.1 75.88,63.93 C644.2 74.22,63.93 73.96,63.66 U42.10
N25622365: length 4.2
  TOP w0.254: R444.1 76,62.91 C644.1 74.1,62.91 73.85,63.16 U42.9
N25675358: length 10
  TOP w0.508: Q7.7 176.33,86.66 176.33,88.19 ; Q7.8 177.48,87.83 177.12,88.19 176.33,88.19 ; 176.33,88.19 174.94,88.19 ; 174.94,88.19 Q7.6 ; 174.94,88.19 174.02,88.19 173.67,87.83 Q7.5
N25696806: length 1.5
  TOP w0.508: D11.A R102.2
N26207329: length 8.7
  TOP w0.127: U21.N3 v2(139.8,71.61)
  BOTTOM w0.127: v2(139.8,71.61) 140.2,71.61 140.52,71.93 140.52,72.57 140.65,72.69 140.65,73.58
  BOTTOM w0.152: 140.65,73.58 140.65,78.03 TP60.1
N26207331: length 7.7
  TOP w0.127: U21.N4 v2(139.8,70.81)
  BOTTOM w0.127: 141.03,75.99 TP61.1 ; 141.03,73.58 141.03,72.44 140.77,72.18 140.77,71.78 v2(139.8,70.81)
  BOTTOM w0.152: 141.03,73.58 141.03,75.99
N26207914: length 14.5
  TOP w0.127: U21.F14 145.8,62.41 v2(146.2,62.01)
  BOTTOM w0.122: 150.55,62.02 149.28,62.02 148.87,61.61 146.59,61.61 v2(146.2,62.01)
  BOTTOM w0.152: TP45.1 158.3,60.63 157.41,61.52 154.36,61.52 153.85,62.02 150.55,62.02
N26207917: length 5.8
  TOP w0.127: U21.F15 145.8,61.61 v2(145.4,61.21)
  BOTTOM w0.122: v2(145.4,61.21) 145.8,60.81 150.37,60.81 TP46.1
N26208803: length 33.9
  TOP w0.127: U21.J3 v2(143.8,71.61)
  L4_INT2 w0.127: v2(143.8,71.61) 144.2,72.01 150.72,72.01 151.19,71.55 158.04,71.55 158.93,70.66 158.93,64.18 165.79,57.33 v1(165.79,56.94)
  BOTTOM w0.152: TP47.1 v1(165.79,56.94)
N26208818: length 25
  TOP w0.127: U21.K4 v2(143,70.81)
  L4_INT2 w0.127: v1(159.44,77.52) 158.17,77.52 156.9,76.25 144.07,76.25 141.79,73.97 141.79,71.42 142.01,71.21 142.59,71.21 v2(143,70.81)
  BOTTOM w0.152: v1(159.44,77.52) 160.08,78.15 TP48.1
N26208833: length 23.4
  TOP w0.127: U21.K3 v2(143,71.61)
  L3_INT1 w0.127: v1(158.81,74.98) 158.55,74.72 154.74,74.72 150.43,70.41 147.63,70.41 147.39,70.17 147.39,69.79 147.22,69.61 146.83,69.61 146.83,69.61 146.6,69.38 146.6,68.99 146.42,68.81 146.03,68.81 145.8,69.04 145.8,69.37 145.79,69.37 145.56,69.61 142.76,69.61 142.59,69.77 142.59,71.21 v2(143,71.61)
  BOTTOM w0.152: TP49.1 v1(158.81,74.98)
N26318609: length 6.7
  TOP w0.122: U21.N5 v2(139.8,70.01)
  BOTTOM w0.122: v2(139.8,70.01) 141,71.21 141,72.03 141.53,72.57 141.53,73.58
  BOTTOM w0.152: TP51.1 141.53,74.72 141.53,73.58
N26607524: length 4.3
  BOTTOM w0.254: R397.1 143.06,3.06 D17.C
N26607549: length 182.7
  TOP w0.254: P2.44 v1(27.95,53.98)
  BOTTOM w0.254: v1(27.95,53.98) 29.52,55.55 37.39,55.55 39.93,58.09 72.32,58.09 76.64,53.77 76.64,6.27 80.45,2.46 106.61,2.46 107.5,1.57 144.71,1.57 146.11,2.97 146.11,6.65 148.14,8.68 R398.1
N26607619: length 4.2
  BOTTOM w0.254: D16.C 150.93,3.07 R398.2
N26607860: length 222.3
  TOP w0.254: P3.44 v1(49.68,142.38)
  BOTTOM w0.254: R397.2 140.39,8.81 138.61,7.03 138.61,3.99 136.84,2.21 107.75,2.21 106.86,3.1 81.08,3.1 77.01,7.17 77.01,54.29 73.21,58.09 73.21,89.2 59.49,102.92 59.49,121.33 48.06,132.76 48.06,140.76 v1(49.68,142.38)
N26620998: length 2.7
  TOP w0.152: P2.30 v1(33.55,57.29)
  BOTTOM w0.152: R415.2 33.71,57.45 v1(33.55,57.29)
N26621001: length 2.7
  TOP w0.152: P2.32 v1(32.75,57.27)
  BOTTOM w0.152: R416.2 32.57,57.45 v1(32.75,57.27)
N26621044: length 2.8
  TOP w0.152: v1(49.59,136.57) 49.38,136.78 P3.30
  BOTTOM w0.152: R418.2 v1(49.59,136.57)
N26621047: length 2.8
  TOP w0.152: v1(49.59,137.72) 49.45,137.58 P3.32
  BOTTOM w0.152: R417.2 49.71,137.84 v1(49.59,137.72)
N26623594: length 24.4
  TOP w0.127: U21.D14 147.39,62.41 v2(147,62.01)
  L4_INT2 w0.127: v1(164.65,51.61) 161.98,51.61 160.58,53.01 159.82,53.01 156.52,56.31 156.52,57.33 155.76,58.09 153.09,58.09 149.57,61.61 147.39,61.61 v2(147,62.01)
  BOTTOM w0.152: TP55.1 165.28,50.98 v1(164.65,51.61)
N26623597: length 23
  TOP w0.127: v2(147.8,62.81) 147.39,63.21 147.39,63.21 U21.D13
  L4_INT2 w0.127: v1(164.27,52.88) 161.85,52.88 160.33,54.4 158.93,54.4 156.9,56.44 156.9,57.45 155.89,58.47 153.22,58.47 149.28,62.41 148.2,62.41 v2(147.8,62.81)
  BOTTOM w0.152: TP56.1 v1(164.27,52.88)
N26623758: length 9.4
  TOP w0.127: v2(135,70.01) U21.W5
  L4_INT2 w0.127: v2(135,70.01) 134.6,70.41 132.13,70.41 129.72,72.82 v1(128.71,72.82)
  BOTTOM w0.152: R432.2 128.2,73.33 v1(128.71,72.82)
N26628373: length 16.6
  TOP w0.127: U21.L4 v2(142.2,70.81)
  BOTTOM w0.122: 131.37,71.42 132.71,70.09
  BOTTOM w0.127: v2(142.2,70.81) 142.2,70.61 141.79,70.21 141.79,69.85 141.22,69.26 137.98,69.26 137.63,69.61 133.19,69.61 132.71,70.09
  BOTTOM w0.152: 131.37,71.42 129.47,73.33 R431.2
N26669713: length 4.4
  TOP w0.279: C638.1 16.57,79.41 16.05,79.93 U45.21
N26669717: length 1.1
  TOP w0.508: 14.28,79.3 C633.2
N26669739: length 2.7
  TOP w0.279: U45.20 15.55,80.43 C633.1
N26669755: length 22.9
  TOP w0.279: R434.2 18.34,81.58 17.55,82.38 U45.24
  TOP w0.381: C632.2 R434.2
  TOP w0.508: C632.2 24.19,79.8 J25.7
  L3_INT1 w0.508: J25.1 J25.3 J25.5 J25.7
N26669803: length 2.9
  TOP w0.279: U45.3 16.55,87.02 16.82,87.3 R435.1
N26669831: length 7.8
  TOP w0.279: R437.2 15.68,88.06 16.05,87.69 U45.4
  TOP w0.508: R437.2 15.42,88.82 14.92,89.33 R436.1
N26669847: length 3.1
  TOP w0.279: C631.1 18.34,87.93 17.05,86.63 U45.2
N26670020: length 2.1
  TOP w0.279: U45.23 17.05,81.48 TP58.1
N26671814: length 3.4
  TOP w0.508: R433.1 J25.8
N26671819: length 3.4
  TOP w0.508: R439.1 J25.6
N26671824: length 3.4
  TOP w0.508: R441.1 J25.4
N26671827: length 3.4
  TOP w0.508: R440.1 J25.2
N26682338: length 4
  TOP w0.508: R96.1 135.31,102.54 135.82,102.03 J19.2
N26683109: length 14.3
  TOP w0.508: J20.2 208.72,132 204.65,136.07 R36.1
N26683821: length 3.2
  TOP w0.508: R436.2 J23.2
N26711184: length 4.5
  TOP w0.254: R447.2 79.05,89.08 78.8,88.82 C645.1 77.27,88.82 77,88.55 U47.10
N26711194: length 4.5
  TOP w0.254: R446.2 78.92,87.42 78.54,87.81 C645.2 77.27,87.81 77.03,88.05 U47.9
N26711585: length 2.3
  TOP w0.152: R448.2 69.54,88.55 U47.1
N26711588: length 2.2
  TOP w0.152: U47.2 69.26,88.05 R449.2
N26712218: length 2.5
  TOP w0.152: R450.2 66.37,63.66 U42.1
N26712221: length 2.3
  TOP w0.152: R451.2 65.71,63.16 U42.2
N26816813: length 4.8
  TOP w0.152: R460.2 198.94,28.12 198.56,28.5 Q29.1
N26817083: length 7.2
  TOP w0.152: R461.1 202.49,24.31 201.86,23.67 198.94,23.67 198.56,24.05 Q30.1
N26884619: length 2.5
  TOP w0.254: v1(158.17,95.81) 158.09,95.89 U48.3
  BOTTOM w0.508: R466.1 158.3,95.68 v1(158.17,95.81)
N26901042: length 4.4
  TOP w0.279: C657.1 41.22,87.55 40.7,87.03 U49.21
N26901046: length 1.3
  TOP w0.508: C652.2 41.33,85.14
N26901068: length 2.7
  TOP w0.279: U49.20 40.19,86.53 C652.1
N26901080: length 12.2
  TOP w0.279: U49.24 38.25,88.53 39.05,89.33 R469.2
  TOP w0.381: C651.2 R469.2
  TOP w0.508: J27.1 39.3,92.12 C651.2
  L3_INT1 w0.508: J27.1 J27.3 J27.5 J27.7
N26901130: length 3
  TOP w0.279: U49.3 32.21,87.53 R470.1
N26901158: length 12.1
  TOP w0.279: U49.4 32.94,87.03 32.31,86.41 R472.2
  TOP w0.508: R471.1 28.89,87.81 29.52,87.17 31.3,87.17 31.81,86.66 R472.2
N26901172: length 3.1
  TOP w0.279: U49.2 33.36,88.03 C650.1
N26901338: length 2.1
  TOP w0.279: TP62.1 39.15,88.03 U49.23
N26901371: length 3.2
  TOP w0.508: R471.2 J26.2
N26901409: length 3.4
  TOP w0.508: R473.1 J27.8
N26901413: length 3.4
  TOP w0.508: R476.1 J27.6
N26901417: length 3.4
  TOP w0.508: R475.1 J27.4
N26901419: length 3.4
  TOP w0.508: R474.1 J27.2

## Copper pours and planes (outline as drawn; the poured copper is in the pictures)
12V on TOP: 15.68,85.65 15.68,87.42 14.28,88.82 11.87,88.82 11.49,89.2 11.49,90.73 13.14,92.38 13.14,93.65 12.88,93.9 9.58,93.9 9.33,93.65 9.33,87.3 9.71,86.92 14.15,86.92 14.41,86.66 14.41,85.65
12V on TOP: 86.8,64.18 86.54,63.93 81.84,63.93 81.21,63.29 81.21,61.77 81.59,61.39 86.54,61.39 86.67,61.52 86.67,62.79 86.8,62.91 87.81,62.91 87.81,64.18
12V on TOP: 101.4,92.63 101.4,95.3 103.31,97.2 105.97,97.2 106.23,96.95 106.23,92.63 105.59,92 102.04,92
12V on TOP: 104.45,43.99 104.45,44.75 103.82,45.39 103.31,45.39 103.05,45.64 103.05,50.98 103.31,51.23 105.34,51.23 105.59,50.98 105.59,45.13 105.72,45.01 105.72,43.99
12V on TOP: 199.07,113.84 197.92,112.7 192.72,112.7 192.59,112.57 192.59,110.54 192.97,110.16 201.35,110.16 201.86,110.67 202.24,110.67 202.49,110.92 202.49,112.44 203,112.95 204.02,112.95 204.02,113.84
12V on TOP: 34.98,86.66 33.2,86.66 31.81,85.27 31.81,82.34 31.55,82.09 28,82.09 27.11,82.98 27.11,93.65 26.85,93.9 24.57,93.9 24.31,93.65 24.31,81.58 25.58,80.31 33.33,80.31 33.71,80.69 33.71,85.14 33.97,85.39 34.98,85.39
12V on TOP: 190.3,134.16 189.67,134.16 189.16,134.67 186.49,134.67 186.37,134.54 186.37,130.1 186.75,129.72 188.52,129.72 189.03,130.22 189.03,133.4 189.41,133.78 190.3,133.78
12V on TOP: 95.31,48.94 96.07,48.94 96.2,49.07 96.2,51.48 96.45,51.74 96.45,56.06 96.58,56.18 97.85,56.18 98.86,55.17 98.86,50.98 98.61,50.72 98.61,49.07 98.23,48.69 97.72,48.69 96.7,47.67 95.31,47.67
12V on BOTTOM: 166.43,105.59 191.57,105.59 191.7,105.46 198.56,105.46 201.48,108.38 201.48,113.59 201.1,113.97 190.94,113.97 190.3,114.6 190.3,127.3 188.78,128.83 188.78,132.26 188.4,132.64 187,132.64 186.62,132.26 186.62,111.05 185.48,109.9 162.24,109.9 151.19,98.85 103.43,98.85 102.8,98.22 102.8,92.89 103.18,92.5 153.35,92.5
12V on L4_INT2: 107.37,97.2 108.13,96.44 108.13,45.64 106.61,44.12 90.35,44.12 85.15,49.32 85.15,61.77 84.51,62.41 33.97,62.41 21.14,75.23 21.14,85.52 19.74,86.92 9.33,86.92 9.33,93.9 33.71,93.9 33.71,78.79 40.32,72.18 56.7,72.18 56.7,86.28 67.68,97.27 82.04,97.27 82.1,97.2 ; 1 cut-out
12V_DECT on TOP: 85.15,104.32 85.27,104.44 85.27,110.54 85.15,110.67 76.38,110.67 75.88,110.16 75.88,104.7 76.26,104.32
12V_DECT on TOP: 62.79,138.35 62.79,147.75 63.18,148.13 64.32,148.13 64.83,147.62 64.83,138.35 64.57,138.1 63.05,138.1
12V_DECT on L4_INT2: 65.33,104.82 65.33,138.61 62.16,141.78 62.16,148.89 62.54,149.27 66.6,149.27 67.37,148.51 67.37,142.16 73.08,136.45 73.08,117.14 79.3,110.92 79.3,104.82 78.8,104.32 65.84,104.32
AVDD_CGA1 on TOP: 93.91,7.16 93.78,7.29 93.78,9.45 94.16,9.83 107.12,9.83 107.12,7.92 106.36,7.16
AVDD_CGA1 on BOTTOM: 164.27,77.01 164.27,63.68 165.03,62.91 166.17,62.91 167.19,63.93 167.19,76.76 166.68,77.26 164.52,77.26
AVDD_CGA1 on L5_PWR: 180.4,91.11 180.4,98.09 173.54,98.09 173.54,101.39 188.52,101.39 188.52,102.92 189.67,104.06 204.65,104.06 204.65,143.05 208.97,143.05 208.97,151.05 214.69,151.05 214.69,24.81 180.52,24.81 180.52,7.8 114.1,7.8 113.47,7.16 103.69,7.16 102.93,7.92 102.93,13.51 103.05,13.64 107.12,13.64 108.64,12.11 175.7,12.11 175.7,31.67 165.79,31.67 165.79,41.07 157.41,49.45 157.41,52.88 150.3,59.99 147.25,59.99 146.74,60.5 145.22,60.5 144.84,60.88 144.58,60.88 144.33,61.14 144.33,65.33 144.84,65.83 156.39,65.83 158.81,68.25 158.81,69.64 158.3,70.15 157.28,70.15 155.71,68.58 144.99,68.58 144.82,68.41 144.82,68.36 143.82,67.36 136.96,67.36 136.71,67.61 136.71,75.23 136.58,75.36 121.98,75.36 121.21,76.12 121.21,79.04 124.14,79.04 130.61,85.52 179.13,85.52 179.13,81.71 185.35,81.71 185.48,81.84 185.48,91.11
GND on TOP: 72.83,115.49 72.83,120.7 72.32,121.21 69.78,121.21 69.53,120.95 69.53,118.29 70.03,117.78 70.92,117.78 71.43,117.27 71.43,115.49 71.68,115.24 72.57,115.24
GND on TOP: 63.3,167.43 68.64,167.43 68.7,167.37 69.72,167.37 71.56,165.53 71.56,151.94 68,148.38 68,137.34 67.75,137.08 65.72,137.08 65.46,137.34 65.46,149.65 68.89,153.08 68.89,157.4 69.27,157.78 69.27,161.21 68.64,161.85 63.43,161.85 63.05,162.23 63.05,167.18
GND on TOP: 107.5,24.81 107.5,16.81 106.86,16.18 103.56,16.18 103.18,15.8 103.18,14.91 103.56,14.53 109.02,14.53 110.17,15.67 110.17,26.34 109.4,27.1 104.83,27.1 104.45,26.72 104.45,25.83 104.7,25.58 106.74,25.58
GND on TOP: 84.26,22.53 84.77,22.02 86.16,22.02 86.54,22.4 86.54,30.91 85.65,31.8 84.64,31.8 84.26,31.42
GND on TOP: 90.61,22.91 90.61,16.81 96.45,16.81 96.45,22.91
GND on TOP: 98.99,10.97 98.99,12.62 99.37,13 107.63,13 108.01,12.62 108.01,11.48 107.37,10.84 99.12,10.84
GND on TOP: 0.95,98.98 0.95,167.43 45.4,167.43 45.4,98.98 ; 2 cut-outs
GND on TOP: 50.48,90.85 50.48,78.92 46.79,75.23 43.36,75.23 42.73,75.87 42.73,79.3 42.35,79.68 37.78,79.68 36.89,80.57 36.89,84.5 36.76,84.63 35.36,84.63 35.24,84.5 35.24,82.85 34.73,82.34 34.73,77.9 40.44,72.18 51.11,72.18 55.56,76.63 55.56,90.85
GND on TOP: 109.4,41.7 102.29,41.7 101.15,40.56 95.31,40.56 94.93,40.94 94.93,42.59 95.05,42.72 100.51,42.72 101.15,43.36 101.15,45.64 100.64,46.15 100.64,50.72 100.77,50.85 101.53,50.85 101.78,50.59 101.78,48.94 102.16,48.56 102.16,46.66 102.55,46.28 102.55,45.39 102.93,45.01 103.82,45.01 104.2,44.63 104.2,43.74 104.45,43.48 107.5,43.48 107.5,44.37 108.51,44.37 109.53,43.36 109.53,41.83
GND on TOP: 0.95,52.25 0.95,8.43 71.81,8.43 71.81,52.25 ; 2 cut-outs
GND on TOP: 18.73,70.15 7.93,70.15 3.99,74.09 3.99,78.15 4.5,78.66 7.42,78.66 7.42,83.36 7.8,83.74 13.52,83.74 13.65,83.87 13.65,85.27 13.52,85.39 11.61,85.39 11.23,85.77 3.99,85.77 1.45,83.23 1.45,69.26 5.64,65.07 18.73,65.07
GND on TOP: 180.4,109.01 192.59,109.01 192.84,108.76 200.21,108.76 200.59,108.38 200.59,106.73 200.21,106.35 192.21,106.35 191.45,105.59 180.78,105.59 180.27,106.09 180.27,108.89
GND on TOP: 85.53,98.09 89.21,98.09 89.59,97.71 89.59,88.44 89.21,88.06 85.15,88.06 84.64,88.57 84.64,97.2
GND on TOP: 85.91,2.72 85.91,10.97 84.89,11.99 82.23,11.99 80.45,10.21 80.45,3.22 81.34,2.33 85.53,2.33
GND on BOTTOM: 124.14,158.8 124.14,155.24 129.22,155.24 129.22,158.8
GND on BOTTOM: 183.95,78.41 190.05,78.41
GND on BOTTOM: 98.86,12.11 93.78,12.11 93.53,12.37 92.13,12.37 91.62,11.86 81.84,11.86 80.45,10.46 80.45,5.76 80.96,5.26 86.04,5.26 88.07,7.29 98.61,7.29 98.99,7.67 98.99,11.99
GND on BOTTOM: 1.45,98.98 1.45,167.43 48.44,167.43 49.08,166.8 49.08,147.11 48.19,146.23 45.65,146.23 45.14,145.72 45.14,120.95 46.67,119.43 52.63,119.43 54.54,117.52 54.54,100.89 52.63,98.98 ; 2 cut-outs
GND on BOTTOM: 101.4,21.13 101.15,20.88 101.15,17.32 100.13,16.3 100.13,12.49 101.66,10.97 107.37,10.97 107.82,11.41 107.82,15.35 103.31,19.86 103.31,20.88 103.05,21.13
GND on BOTTOM: 78.54,127.81 87.94,127.81 88.96,126.79 88.96,124.64 88.32,124 87.43,124 87.05,123.62 87.05,118.54 86.54,118.03 82.61,118.03 82.23,118.41 82.23,121.71 82.48,121.97 85.4,121.97 85.65,122.22 85.65,123.75 85.15,124.25 78.29,124.25 78.03,124.51 78.03,127.3
GND on BOTTOM: 163.76,156.26 168.2,156.26 168.46,156 168.46,153.21 167.82,152.58 163.89,152.58 163.51,152.96 163.51,156
GND on BOTTOM: 110.85,157.55 118.6,157.55 119.11,157.05 119.11,153.87 118.47,153.24 111.11,153.24 110.6,153.74 110.6,157.3
GND on BOTTOM: 104.07,159.69 101.66,159.69 101.28,159.31 101.28,152.96 100.77,152.45 99.5,152.45 99.12,152.83 99.12,161.34 100.01,162.23 103.82,162.23 104.45,161.59 104.45,160.07
GND on BOTTOM: 100.89,88.31 106.99,88.31
GND on BOTTOM: 1.07,8.56 71.81,8.56 71.81,52.5 71.68,52.5 71.68,56.31 71.05,56.94 49.46,56.94 48.7,56.18 48.7,52.63 48.57,52.5 24.82,52.5 23.04,54.28 23.04,63.29 21.39,64.95 1.2,64.95 1.07,64.82 ; 2 cut-outs
